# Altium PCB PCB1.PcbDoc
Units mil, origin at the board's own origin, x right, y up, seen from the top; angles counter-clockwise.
Board outline 3523.62 x 1496.06 mil, 2 copper layers (Top Layer, Bottom Layer), stack 65.792 mil thick; 25 components, 24 nets, 86 pads, 26 vias.
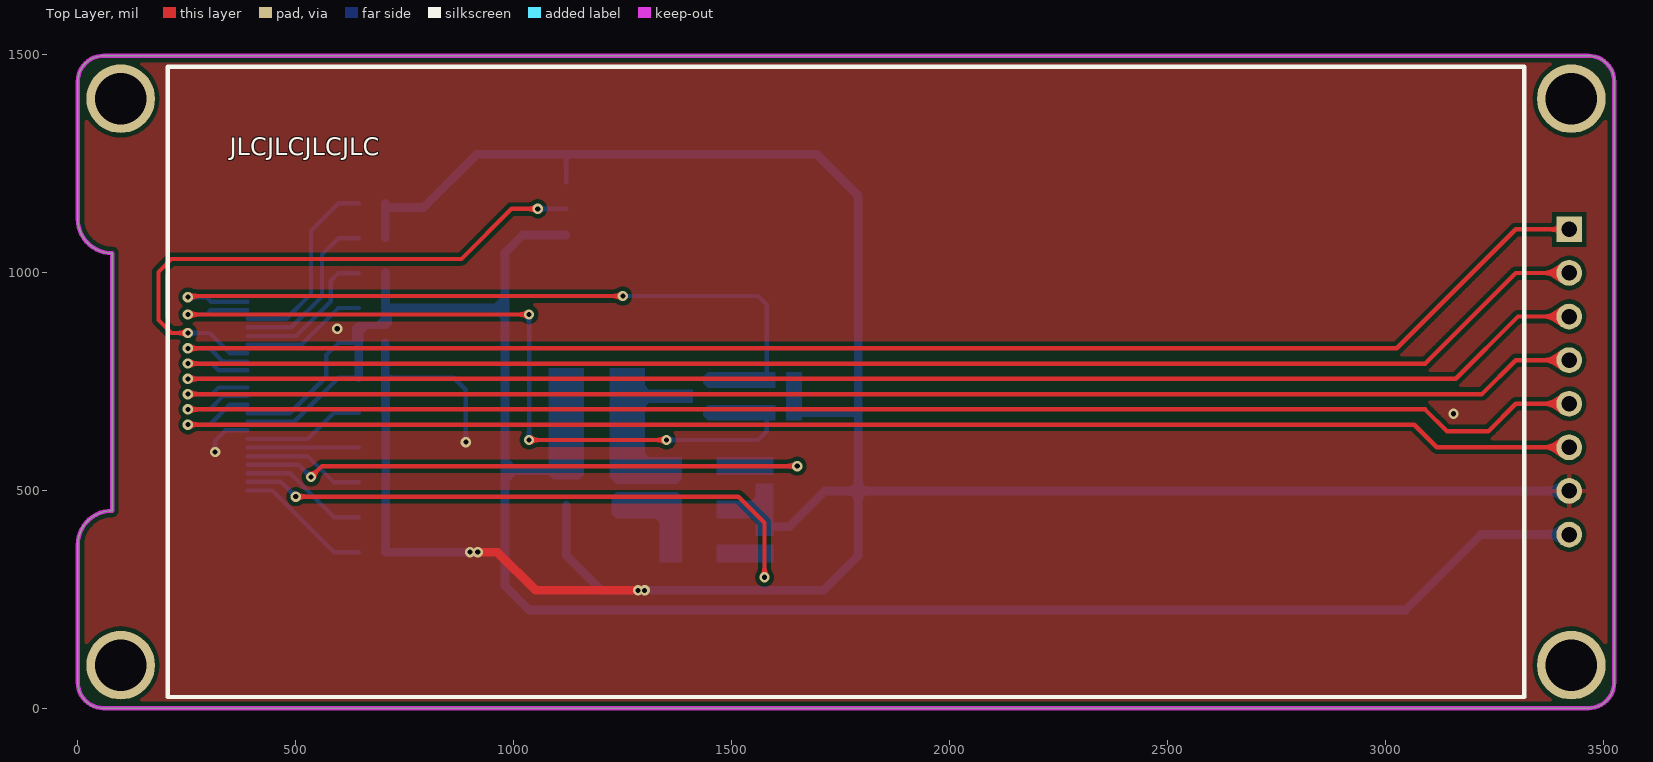
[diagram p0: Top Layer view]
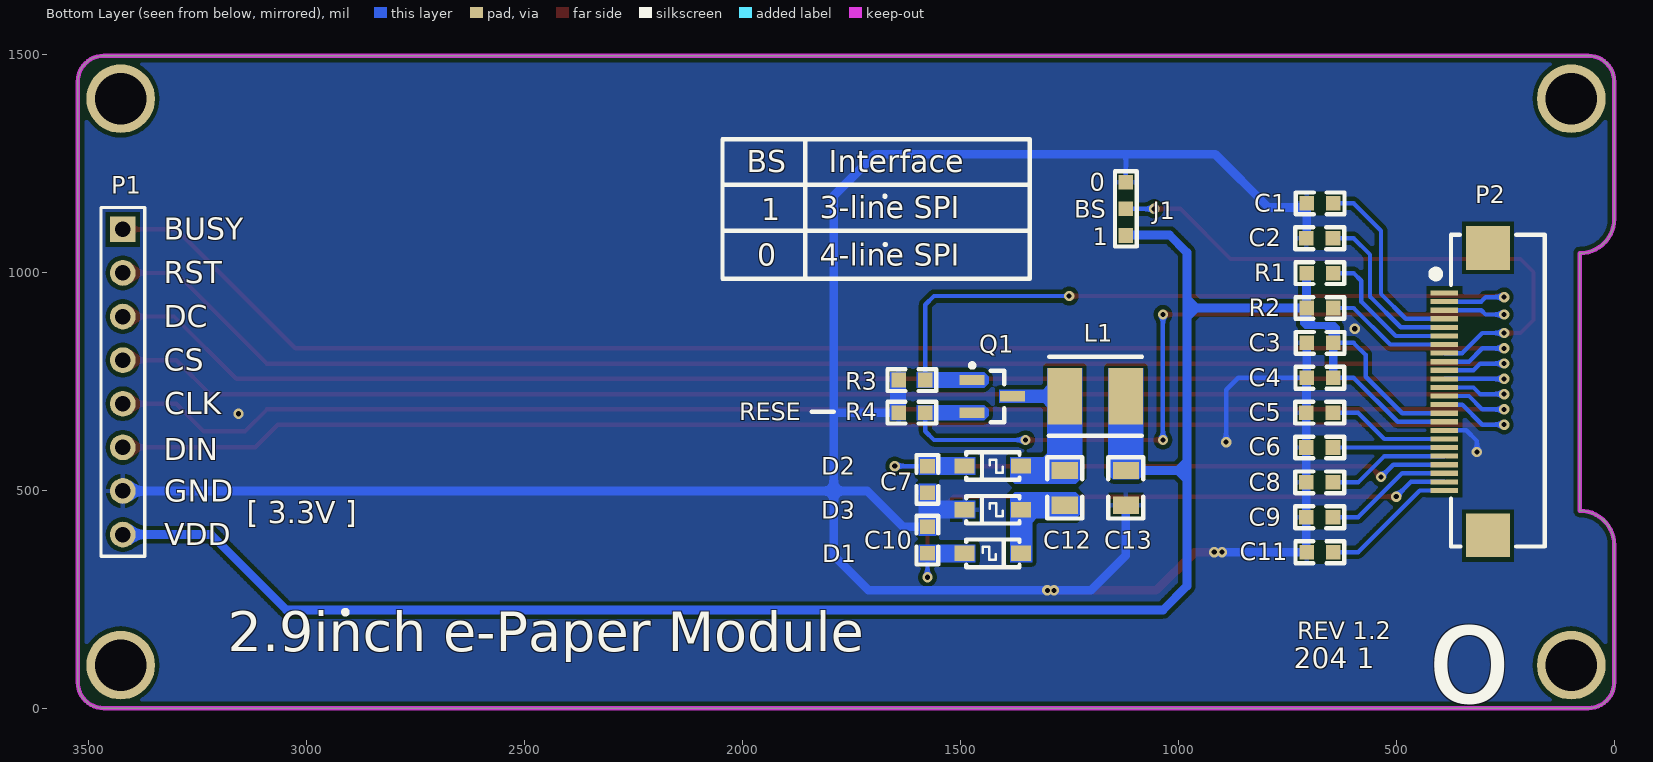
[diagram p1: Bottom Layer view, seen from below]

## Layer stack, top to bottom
Top Solder: solder mask 0.4, Solder Resist, Dk 3.5
Top Layer: signal copper 1.4
Dielectric 1: dielectric 62.9921, FR-4, Dk 4.8
Bottom Layer: signal copper 1.4
Bottom Solder: solder mask 0.4, Solder Resist, Dk 3.5

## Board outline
0,59.06 0,374.02 cw(c78.74,374.02) 78.74,452.76 78.74,1043.31 cw(c78.74,1122.05) 0,1122.05 0,1437.01 cw(c59.06,1437.01) 59.06,1496.06 3464.57,1496.06 cw(c3464.57,1437.01) 3523.62,1437.01 3523.62,59.06 cw(c3464.57,59.06) 3464.57,0 59.06,0 cw(c59.06,59.06)

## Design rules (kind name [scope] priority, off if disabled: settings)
BoardOutlineClearance [All] p1: gap=7.87 ignorepadtopadclearanceinfootprint=FALSE
Clearance Clearance_po [InPolygon] p1: gap=10 ignorepadtopadclearanceinfootprint=FALSE
Clearance [All] p2: gap=5 ignorepadtopadclearanceinfootprint=FALSE
HoleSize [All] p1: absolutevalues=TRUE maxlimit=248.03 minlimit=0.98 maxpercent=80.000 minpercent=20.000
HoleToHoleClearance [All] p1: gap=0 allowstackedmicrovias=TRUE
MinimumSolderMaskSliver [All] p1: minsoldermaskwidth=0
PolygonConnect [All] p1: thpad.connectstyle=Relief thpad.reliefconductorwidth=10 thpad.reliefentries=4 thpad.polygonreliefangle="90 Angle" thpad.airgapwidth=10 smdpad.connectstyle=Relief smdpad.reliefconductorwidth=10 smdpad.reliefentries=4 smdpad.polygonreliefangle="90 Angle" smdpad.airgapwidth=10 via.connectstyle=Direct via.reliefconductorwidth=10 via.reliefentries=4 via.polygonreliefangle="90 Angle" via.airgapwidth=10
RoutingVias [All] p1: holewidth=11.81 width=23.62 viastyle="Through Hole" minholewidth=11.81 minwidth=23.62 maxholewidth=248.03 maxwidth=787.4
SilkToSilkClearance [All] p1: silktosilkclearance=0
SilkToSolderMaskClearance [IsPad] p1: minsilkscreentomaskgap=0 clearancetoexposedcopper=TRUE
SolderMaskExpansion [All] p1: expansion=2 istentingtop=FALSE
Width [All] p1: maxlimit=100 minlimit=5 preferedwidth=10
25 further rules are at their usual default settings.

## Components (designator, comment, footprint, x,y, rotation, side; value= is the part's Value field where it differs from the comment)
C1 "1uf 25v" 0603-CAP 674.49,1157.64 r180 bottom
C2 "1uf 25v" 0603-CAP 675.51,1077.64 r180 bottom
C3 "0.1uf 25v" 0603-CAP 674.49,837.64 r180 bottom
C4 "1uf 25v" 0603-CAP 675,757.64 r180 bottom
C5 "1uf 25v" 0603-CAP 675.51,677.64 r180 bottom
C6 "1uf 25v" 0603-CAP 675.51,597.64 r180 bottom
C7 "1uf 50v" 0603-CAP 1575,524.49 r90 bottom
C8 "1uf 25v" 0603-CAP 675.51,517.64 r180 bottom
C9 "1uf 25v" 0603-CAP 675.51,437.64 r180 bottom
C10 "1uF 50v" 0603-CAP 1575,385.51 r270 bottom
C11 "1uf 6v" 0603-CAP 675,357.64 r180 bottom
C12 "4.7uF 50v" 0805-CAP 1260,505 r90 bottom
C13 "10uf 6v" 0805-CAP 1120,505 r90 bottom
D1 "MBR0530" SOD-123-DIODE-SC_M 1425,355 r180 bottom
D2 "MBR0530" SOD-123-DIODE-SC_M 1425,555 r0 bottom
D3 "MBR0530" SOD-123-DIODE-SC_M 1425,455 r0 bottom
J1 "Jumper-0603" 0603-JUMPER 1120,1145 r270 bottom
L1 "47uH" NR_4020_M 1190,715 r180 bottom
P1 "Male-1X8-2.54mm" MALE_1X8_2.54MM 3420.28,748.03 r270 bottom locked
P2 "FPC-24P-0.5mm" "FPC0.5 2H-WS-24P_M" 289.41,725.59 r270 bottom locked
Q1 "NMOS" SOT-23-3_M 1426.26,715 r180 bottom
R1 "10k" 0603-RES 675,997.64 r180 bottom
R2 "10k" 0603-RES 675,917.64 r180 bottom
R3 "100K" 0603-RES 1610.51,752.4 r180 bottom
R4 "4.7R" 0603-RES 1610.51,677.6 r180 bottom

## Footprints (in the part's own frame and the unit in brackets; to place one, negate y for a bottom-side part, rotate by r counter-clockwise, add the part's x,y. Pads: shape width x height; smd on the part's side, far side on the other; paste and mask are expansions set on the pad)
0603-CAP [mm]
  rect 0.85x0.85 smd: 1(-0.775,0) 2(0.775,0)
  silkscreen extent -1.42,-0.64 1.42,0.64, body extent -0.8,-0.4 0.8,0.4, height 0.7
0603-JUMPER [mm]
  rect 0.85x0.85 smd: 1(-1.55,0) 2(0,0) 3(1.55,0)
  silkscreen extent -2.2,-0.64 2.2,0.64
0603-RES [mm]
  rect 0.85x0.85 smd: 1(-0.775,0) 2(0.775,0)
  silkscreen extent -1.42,-0.64 1.42,0.64, body extent -0.85,-0.4 0.85,0.4, height 0.56
0805-CAP [mil]
  rect 40x60 smd: 1(-40,0) 2(40,0)
  silkscreen extent -70,-40 70,40, body extent -39,-25 39,25, height 31
"FPC0.5 2H-WS-24P_M" [mm]
  rect 0.3x1.6 smd: 1(-5.75,-2.54) 2(-5.25,-2.54) 3(-4.75,-2.54) 4(-4.25,-2.54) 5(-3.75,-2.54) 6(-3.25,-2.54) 7(-2.75,-2.54) 8(-2.25,-2.54) 9(-1.75,-2.54) 10(-1.25,-2.54) 11(-0.75,-2.54) 12(-0.25,-2.54) 13(0.25,-2.54) 14(0.75,-2.54) 15(1.25,-2.54) 16(1.75,-2.54) 17(2.25,-2.54) 18(2.75,-2.54) 19(3.25,-2.54) 20(3.75,-2.54) 21(4.25,-2.54) 22(4.75,-2.54) 23(5.25,-2.54) 24(5.75,-2.54)
  rect 2.54x2.54 smd: 25(8.371,0) 26(-8.371,0)
  silkscreen extent -9.14,-3.23 9.02,3.3, body extent -8.1,-2.85 8.1,3.15, height 2
MALE_1X8_2.54MM [mm]
  rect 1.5x1.5 hole 0.9: 1(-8.89,0)
  round 1.5 hole 0.9: 2(-6.35,0) 3(-3.81,0) 4(-1.27,0) 5(1.27,0) 6(3.81,0) 7(6.35,0) 8(8.89,0)
  silkscreen extent -10.16,-1.27 10.16,1.27, body extent -10.16,-1.27 10.16,1.27, height 8.58
NR_4020_M [mm]
  rect 2x3.3 smd: 1(-1.778,0) 2(1.778,0)
  silkscreen extent -2.71,-2.29 2.72,2.31, body extent -2,-2 2,2, height 2.1
SOD-123-DIODE-SC_M [mil]
  rect 45.75x35 smd: 1(64.91,0) 2(-64.91,0)
  silkscreen extent -61,-32 61,32, body extent -65,-31 65,31, height 47
SOT-23-3_M [mm]
  rect 1.45x0.6 smd: 1(-1.175,0.95) 2(-1.175,-0.95) 3(1.175,0)
  silkscreen extent -1.3,-1.5 0.7,1.92, body extent -1.25,-1.5 1.25,1.5, height 0.98

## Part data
C1 C2 C3 C4 C5 C6 C7 C8 C9 C10 C11: library part CAP-0603
C12 C13: library part CAP-0805
D1 D2 D3: library part Diode-Schottky-SOD123
L1: library part Inductor-NR4020
Q1: library part NMOS-SOT23-3
R1 R2 R3 R4: library part RES-0603

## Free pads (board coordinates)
  round 157.48 hole 118.11: ""(98.43,98.43) ""(98.43,1397.64) ""(3425.2,98.43) ""(3425.2,1397.64)

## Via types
v1: diameter 23.62, hole 11.81, Top Layer to Bottom Layer, tented both sides, 26 vias

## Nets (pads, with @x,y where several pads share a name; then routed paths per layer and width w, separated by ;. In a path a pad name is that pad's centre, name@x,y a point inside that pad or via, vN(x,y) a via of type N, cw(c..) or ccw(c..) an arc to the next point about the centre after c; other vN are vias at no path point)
BS1: J1.2 P2.8 | length 1340.9
  Top Layer w10: v1(252.56,860.12) 214.88,860.12 185,890 185,1000 215,1030 880,1030 995,1145 v1(1055,1145)
  Bottom Layer w10: v1(252.56,860.12) 302.44,860.12 348.39,814.17 P2.8 ; v1(1055,1145) J1.2
BUSY: P1.1 P2.9 | length 3430.3
  Top Layer w10: v1(252.56,825.12) 3025.12,825.12 3298.03,1098.03 P1.1
  Bottom Layer w10: v1(252.56,825.12) 302.44,825.12 333.07,794.49 P2.9
CLK: P1.5 P2.13 | length 3364.1
  Top Layer w10: v1(252.56,685.12) 3089.88,685.12 3140,635 3235,635 3298.03,698.03 P1.5
  Bottom Layer w10: v1(252.56,685.12) 302.56,685.12 333.19,715.75 P2.13
CS: P1.4 P2.12 | length 3343.2
  Top Layer w10: v1(252.56,720.12) 3220.12,720.12 3298.03,798.03 P1.4
  Bottom Layer w10: v1(252.56,720.12) 307.56,720.12 322.87,735.43 P2.12
DC: P1.3 P2.11 | length 3363.8
  Top Layer w10: v1(252.56,755.12) 3160.12,755.12 3303.03,898.03 P1.3
  Bottom Layer w10: v1(252.56,755.12) P2.11
DIN: P1.6 P2.14 | length 3345.2
  Top Layer w10: v1(252.56,650.12) 3064.88,650.12 3116.61,598.39 3419.91,598.39 P1.6
  Bottom Layer w10: v1(252.56,650.12) 302.56,650.12 348.5,696.06 P2.14
GND: C1.1 C2.1 C3.1 C4.1 C5.1 C6.1 C7.1 C8.1 C9.1 C10.1 C11.1 C13.1 D3.1 J1.1 P1.7 P2.17 R3.1 R4.1 | length 6563.2
  Top Layer w20: v1(899.33,357.64) v1(917.36,357.64) 962.36,357.64 1050,270 v1(1285,270)
  Bottom Layer w10: v1(315,587.56) 315,612.56 339.45,637.01 P2.17 ; C4.1@705,758.15 C4.1 862.36,757.64 890,730 v1(890,610) ; C2.1@705,1078.66 C2.1 ; J1.1 1120,1270 ; 1787.6,677.6 1790,680
  Bottom Layer w20: C4.1@705,758.15 C3.1 ; C2.1@705,1078.66 C1.1@705,1148.03 ; C1.1 C1.1@705,1148.03 ; C11.1 v1(917.36,357.64) ; C5.1@705.51,678.15 C4.1 ; C11.1@706.02,358.15 C9.1 C8.1 C6.1 C5.1 ; C13.1 1120,350 1200,270 v1(1285,270) v1(1300,270) 1710,270 1790,350 1790,498.03 ; C10.1 1631.02,416.02 1713.03,498.03 1790,498.03 ; R4.1 1787.6,677.6 ; P1.7 1790,498.03 ; C1.1@705,1148.03 793.03,1148.03 915,1270 1120,1270 1695,1270 1790,1175 1790,680 1790,498.03
  other v1: 3155,675 595,870
NetC1_2: C1.2 P2.4 | length 449.2
  Bottom Layer w10: P2.4 477.91,892.91 535,950 535,1095 597.64,1157.64 C1.2
NetC2_2: C2.2 P2.5 | length 396.6
  Bottom Layer w10: P2.5 489.49,873.23 560,943.74 560,1040 597.64,1077.64 C2.2
NetC5_2: C5.2 P2.18 | length 280.6
  Bottom Layer w10: P2.18 527.32,617.32 587.64,677.64 C5.2
NetC6_2: C6.2 P2.19 | length 255.6
  Bottom Layer w10: P2.19 C6.2
NetC7_2: C7.2 D2.1 P2.21 | length 1357.7
  Top Layer w10: v1(535,530) 560,555 v1(1650,555)
  Bottom Layer w10: P2.21 506.73,558.27 v1(535,530) ; C7.2 v1(1650,555)
NetC8_2: C8.2 P2.20 | length 280.6
  Bottom Layer w10: P2.20 527.05,577.95 587.36,517.64 C8.2
NetC9_2: C9.2 P2.22 | length 297.4
  Bottom Layer w10: P2.22 486.42,538.58 587.36,437.64 C9.2
NetC10_2: C10.2 D1.2 P2.23 | length 1404.5
  Top Layer w10: v1(500,485) 1515,485 1575,425 v1(1575,300)
  Bottom Layer w10: P2.23 466.1,518.9 v1(500,485) ; v1(1575,300) C10.2
NetC11_2: C11.2 P2.24 | length 313.7
  Bottom Layer w10: P2.24 445.79,499.21 587.36,357.64 C11.2
NetC12_1: C12.1 D1.1 D3.2
NetC12_2: C12.2 D2.2 L1.1 Q1.3
NetP2_2: P2.2 Q1.1 R3.2 | length 1650.4
  Top Layer w10: v1(252.56,942.56) 255,945 v1(1250,945)
  Bottom Layer w10: v1(252.56,942.56) 294.72,942.56 305,932.28 P2.2 ; v1(1250,945) 1560,945 1580,925 R3.2
NetP2_3: P2.3 Q1.2 R4.2 | length 1806.9
  Top Layer w10: v1(252.56,902.56) v1(1035,902.56) ; v1(1035,615) v1(1350,615)
  Bottom Layer w10: v1(252.56,902.56) 295,902.56 305.04,912.6 P2.3 ; v1(1035,615) v1(1035,902.56) ; v1(1350,615) 1560,615 1580,635 R4.2
NetP2_6: P2.6 R1.2 | length 342.7
  Bottom Layer w10: P2.6 501.3,853.54 580,932.24 580,980 597.64,997.64 R1.2
NetP2_7: P2.7 R2.2 | length 289.8
  Bottom Layer w10: P2.7 513.86,833.86 597.64,917.64 R2.2
RST: P1.2 P2.10 | length 3397
  Top Layer w10: v1(252.56,790.12) 3090.12,790.12 3298.03,998.03 P1.2
  Bottom Layer w10: v1(252.56,790.12) 307.44,790.12 322.76,774.8 P2.10
VCC: C3.2 C4.2 C13.2 J1.3 L1.2 P1.8 P2.15 P2.16 R1.1 R2.1 | length 4678.2
  Bottom Layer w10: P2.16 496.69,656.69 597.64,757.64 C4.2 ; P2.15 486.38,676.38 570,760 570,810 597.64,837.64 C3.2 ; J1.3@1118.98,1085 J1.3
  Bottom Layer w20: C4.2 C3.2@644.49,837.13 ; R1.1 R2.1 980,917.64 ; J1.3@1118.98,1085 1020,1085 980,1045 980,917.64 ; C13.2 980,545 ; P1.8 3218.03,398.03 3045,225 1035,225 980,280 980,545 ; 980,545 980,917.64
pads on no net: P2.1 P2.25 P2.26

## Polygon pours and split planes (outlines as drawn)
GND on Top Layer "GND_L01_P000" (hatched Horizontal grid 1 track 8, remove dead copper, pour order 0): 2.5,1492.5 0,1490 0,0 3525,0 3525,1495
GND on Bottom Layer "GND_L02_P001" (hatched Horizontal grid 1 track 8, remove dead copper, pour order 1): 2.5,1487.5 0,1485 0,-5 3525,-5 3525,1490

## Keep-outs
Keep-Out Layer:
  the board outline again, w10

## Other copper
Bottom Layer:
  region net VCC: 955,907.64 970,892.64 980,892.64 980,942.64 970,942.64 955,927.64
  region net VCC: 1005,555 990,570 980,570 980,520 990,520 1005,535
  region net VCC: 695,910 695,895 685,885 640,885 630,875 630,840 655,840 655,860 665,870 710,870 720,880 720,910
  region net GND: 1625,770 1660,770 1660,660 1625,660
  region net GND: 1465,475 1545,475 1555,485 1555,515 1595,515 1595,395 1555,395 1555,425 1545,435 1465,435
  region net NetC10_2: 1595,335 1465,335 1465,375 1595,375
  region net NetC12_1: 1385,435 1385,335 1335,335 1335,425 1325,435
  region net NetC7_2: 1595,535 1465,535 1465,575 1595,575
  region net NetP2_2: 1600,734.8 1445,734.8 1435,744.8 1435,759.8 1445,769.8 1600,769.8
  region net NetP2_3: 1600,660 1445,660 1435,670 1435,685 1445,695 1600,695
  region net NetC12_2: 1410,700 1310,700 1300,690 1295,690 1295,720 1295,740 1300,740 1310,730 1410,730
  region net NetC12_2: 1300,780 1300,585 1310,575 1220,575 1220,780
  region net VCC: 1160,780 1160,535 1150,525 1090,525 1080,535 1080,780
  region net NetC12_2: 1385,575 1220,575 1220,560 1220,530 1235,515 1375,515 1385,525
  region net NetC12_1: 1375,435 1235,435 1225,445 1225,485 1235,495 1375,495 1385,485 1385,435

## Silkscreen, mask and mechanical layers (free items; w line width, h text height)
Top Overlay:
  lines w10: 206.69,25.59 206.69,1470.47 3316.93,1470.47 3316.93,25.59 206.69,25.59
  text "JLCJLCJLCJLC" at 348,1268 h40
Bottom Overlay:
  circle w10: c1671.93,1063.38 r1
  circle w10: c1672.6,1174.01 r1
  circle w10: c2910,220 r5
  lines w10: 1340,1095 2045,1095 ; 1340,1200 2045,1200 ; 1790,680 1840,680 ; 1855,990 1855,1305 ; 1340,985 1340,1305 2045,1305 2045,985 1340,985
  text "Interface" at 1801,1229 h50
  text "BS" at 1989.98,1228.4 h50
  text "0" at 1203,1187 h40
  text "BS" at 1238.42,1124.09 h40
  text "3-line SPI" at 1821.83,1124 h50
  text "1" at 1956.66,1119 h50
  text "BUSY" at 3326,1074 h50
  text "1" at 1196.34,1062 h40
  text "4-line SPI" at 1821.83,1014 h50
  text "0" at 1964.99,1014.14 h50
  text "RST" at 3326,974 h50
  text "DC" at 3326,874 h50
  text "CS" at 3326,774 h50
  text "CLK" at 3324.98,673.4 h50
  text "RESE" at 2006.71,660.01 h40
  text "DIN" at 3326,569 h50
  text "GND" at 3324.98,473.4 h50
  text "[ 3.3V ]" at 3136,424 h50
  text "VDD" at 3324.98,373.4 h50
  text "REV 1.2" at 727,158 h40
  text "2.9inch e-Paper Module" at 3180,129.99 h90
  text "204 1" at 734.93,75 h80
  text "o" at 430,-64.42 h400
Mechanical 1:
  the board outline again, w10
